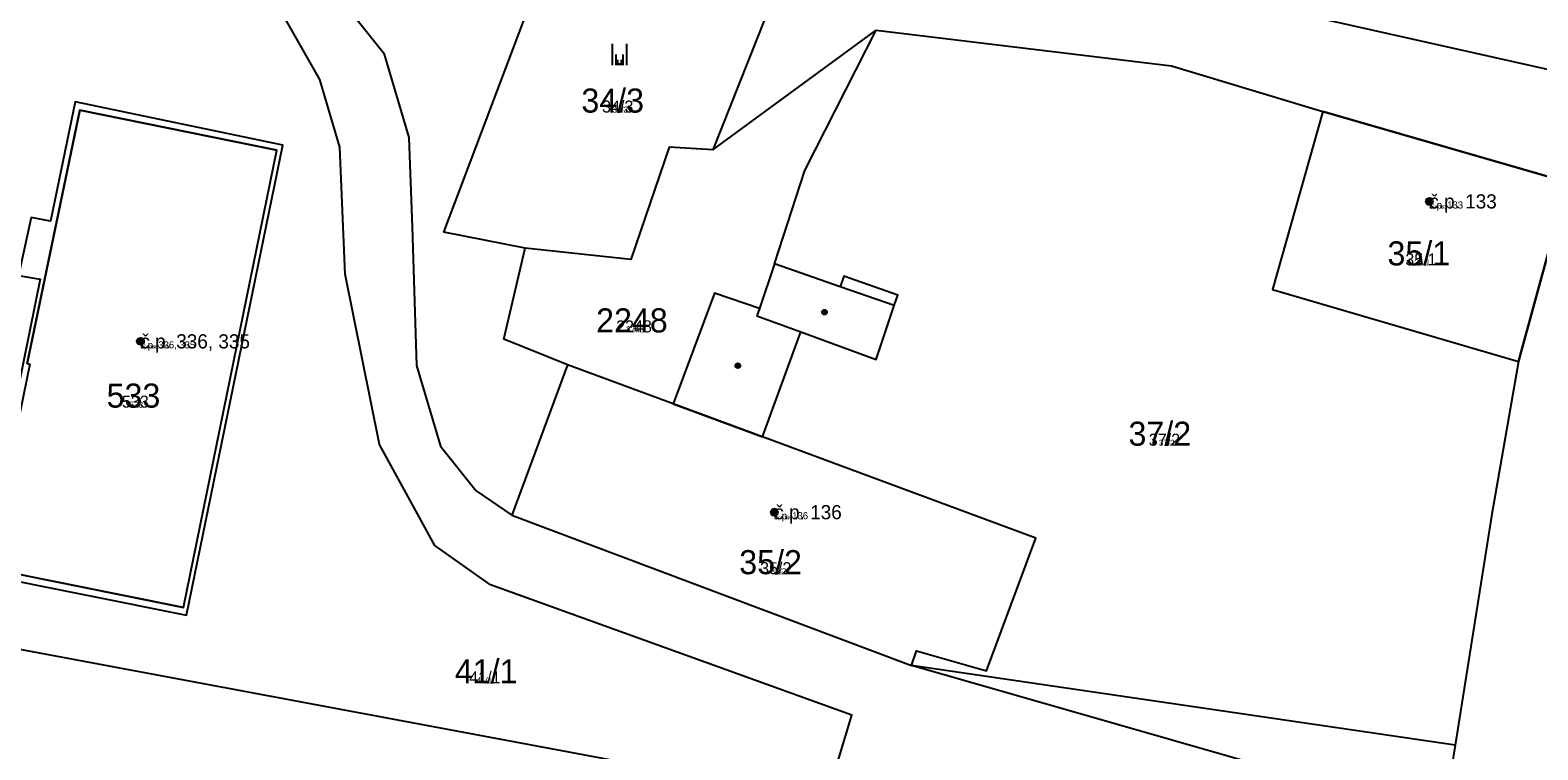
# Model space of a CAD drawing. Extents: x -744652 to -739090, y -980828 to -975855.
# Drawn here: x -742619.3 to -742512.8, y -978574.2 to -978523.4 of the extents above; entities that cross this region are included whole.
import ezdxf

# ---------------------------------------------------------------- set-up
doc = ezdxf.new("R2010")
doc.units = 0
for name, color, linetype in [('KAT_02_hranice parcel', 7, 'Continuous'), ('KAT_03_1000_st čísla parcelní', 7, 'Continuous'), ('KAT_03_1000_čísla parcelní', 7, 'Continuous'), ('KAT_03_1000_čísla popisná', 7, 'Continuous'), ('KAT_03_100_st čísla parcelní', 7, 'Continuous'), ('KAT_03_100_čísla parcelní', 7, 'Continuous'), ('KAT_03_100_čísla popisná', 7, 'Continuous'), ('KAT_03_250_st čísla parcelní', 7, 'Continuous'), ('KAT_03_250_čísla parcelní', 7, 'Continuous'), ('KAT_03_250_čísla popisná', 7, 'Continuous'), ('KAT_03_500_st čísla parcelní', 7, 'Continuous'), ('KAT_03_500_čísla parcelní', 7, 'Continuous'), ('KAT_03_500_čísla popisná', 7, 'Continuous'), ('KAT_04_vnitřní kresba', 7, 'Continuous'), ('KAT_05_1000_značky kultur', 7, 'Continuous'), ('KAT_05_100_značky kultur', 7, 'Continuous'), ('KAT_05_250_značky kultur', 7, 'Continuous'), ('KAT_05_500_značky kultur', 7, 'Continuous'), ('KAT_07_1000_značky budov', 7, 'Continuous'), ('KAT_07_100_značky budov', 7, 'Continuous'), ('KAT_07_500_značky budov', 7, 'Continuous'), ('KAT_14_plocha_budovy', 7, 'Continuous')]:
    doc.layers.add(name, color=color, linetype=linetype)

msp = doc.modelspace()

# ---------------------------------------------------------------- linework, layer by layer
at = {"layer": 'KAT_02_hranice parcel'}
for p, q in [((-742566.17, -978519.49), (-742571.06, -978531.84)), ((-742571.06, -978531.84), (-742559.54, -978523.41)), ((-742581.32, -978547.02), (-742585.26, -978557.63)), ((-742585.26, -978557.63), (-742557.03, -978568.25)), ((-742519.46, -978579.01), (-742557.03, -978568.25)), ((-742518.64, -978573.88), (-742557.03, -978568.25)), ((-742518.64, -978573.88), (-742519.46, -978579.01))]:
    msp.add_line(p, q, dxfattribs=at)
for points in [[(-742598.56, -978509.34), (-742606.7, -978509.52), (-742594.3, -978525.03), (-742592.54, -978530.97), (-742592.31, -978537.31), (-742591.99, -978547.07), (-742590.29, -978552.78), (-742587.77, -978555.92), (-742585.26, -978557.63)], [(-742520.5, -978587.81), (-742525.48, -978582.81), (-742528, -978581.12), (-742545.21, -978576.36), (-742546.31, -978580.73), (-742562.58, -978576.21), (-742561.25, -978571.75), (-742586.77, -978562.57), (-742590.71, -978559.78), (-742594.6, -978552.66), (-742597.04, -978540.63), (-742597.4, -978531.66), (-742598.83, -978526.88), (-742601.73, -978521.76), (-742606.95, -978517.23), (-742612.97, -978513.89), (-742622.3, -978510.73)], [(-742504.65, -978513.37), (-742508.75, -978526.92), (-742531.88, -978521.75), (-742534.32, -978519.68)], [(-742584.33, -978538.79), (-742590.07, -978537.66), (-742581.76, -978515.66), (-742566.17, -978519.49)], [(-742566.72, -978539.89), (-742564.56, -978533.31), (-742559.54, -978523.41)], [(-742559.54, -978523.41), (-742538.68, -978525.92), (-742527.99, -978529.15)], [(-742620.11, -978540.71), (-742618.57, -978540.99), (-742622.81, -978561.78), (-742608.23, -978564.71), (-742601.44, -978531.52), (-742616.11, -978528.47), (-742617.85, -978536.89), (-742619.2, -978536.62), (-742620.11, -978540.71)], [(-742527.99, -978529.15), (-742531.55, -978541.72), (-742514.17, -978546.79)], [(-742527.99, -978529.15), (-742510.7, -978534.14), (-742514.17, -978546.79)], [(-742571.06, -978531.84), (-742574.15, -978531.67), (-742576.86, -978539.59), (-742584.33, -978538.79)], [(-742581.32, -978547.02), (-742585.83, -978545.21), (-742584.33, -978538.79)], [(-742566.72, -978539.89), (-742567.78, -978543.06), (-742570.95, -978541.97), (-742573.86, -978549.78), (-742581.32, -978547.02)], [(-742557.03, -978568.25), (-742556.69, -978567.23), (-742551.75, -978568.62), (-742548.25, -978559.27), (-742567.57, -978552.11), (-742564.86, -978544.7), (-742559.54, -978546.66), (-742558.25, -978542.84), (-742558, -978542.1), (-742561.81, -978540.77), (-742562.08, -978541.51), (-742566.72, -978539.89)], [(-742514.17, -978546.79), (-742516.04, -978557.56), (-742518.64, -978573.88)], [(-742639.54, -978563.45), (-742574.84, -978575.54), (-742583.67, -978623.81)]]:
    msp.add_lwpolyline(points, dxfattribs=at)
at = {"layer": 'KAT_03_1000_čísla popisná'}
for centre in [(-742520.46, -978535.49), (-742520.46, -978535.49), (-742611.49, -978545.37), (-742611.49, -978545.37), (-742566.72, -978557.43), (-742566.72, -978557.43)]:
    msp.add_circle(centre, 0.25, dxfattribs=at)
at = {"layer": 'KAT_03_100_čísla popisná'}
for centre in [(-742520.46, -978535.49), (-742520.46, -978535.49), (-742611.49, -978545.37), (-742611.49, -978545.37), (-742566.72, -978557.43), (-742566.72, -978557.43)]:
    msp.add_circle(centre, 0.025, dxfattribs=at)
at = {"layer": 'KAT_03_250_čísla popisná'}
for centre in [(-742520.46, -978535.49), (-742520.46, -978535.49), (-742611.49, -978545.37), (-742611.49, -978545.37), (-742566.72, -978557.43), (-742566.72, -978557.43)]:
    msp.add_circle(centre, 0.0625, dxfattribs=at)
at = {"layer": 'KAT_03_500_čísla popisná'}
for centre in [(-742520.46, -978535.49), (-742520.46, -978535.49), (-742611.49, -978545.37), (-742611.49, -978545.37), (-742566.72, -978557.43), (-742566.72, -978557.43)]:
    msp.add_circle(centre, 0.125, dxfattribs=at)
at = {"layer": 'KAT_04_vnitřní kresba'}
for p, q in [((-742619.49, -978546.93), (-742615.78, -978529.04)), ((-742615.78, -978529.04), (-742601.87, -978531.88)), ((-742608.46, -978564.17), (-742601.87, -978531.88)), ((-742558.25, -978542.84), (-742562.08, -978541.51)), ((-742567.78, -978543.06), (-742567.95, -978543.56)), ((-742567.95, -978543.56), (-742564.86, -978544.7)), ((-742573.86, -978549.78), (-742567.57, -978552.11)), ((-742608.46, -978564.17), (-742622.23, -978561.39))]:
    msp.add_line(p, q, dxfattribs=at)
at = {"layer": 'KAT_05_1000_značky kultur'}
for p, q in [((-742578.15, -978525.87), (-742578.15, -978524.37)), ((-742577.15, -978525.87), (-742577.15, -978524.37))]:
    msp.add_line(p, q, dxfattribs=at)
at = {"layer": 'KAT_05_100_značky kultur'}
for p, q in [((-742577.69, -978525.87), (-742577.69, -978525.72)), ((-742577.59, -978525.87), (-742577.59, -978525.72))]:
    msp.add_line(p, q, dxfattribs=at)
at = {"layer": 'KAT_05_250_značky kultur'}
for p, q in [((-742577.77, -978525.87), (-742577.77, -978525.49)), ((-742577.52, -978525.87), (-742577.52, -978525.49))]:
    msp.add_line(p, q, dxfattribs=at)
at = {"layer": 'KAT_05_500_značky kultur'}
for p, q in [((-742577.9, -978525.87), (-742577.9, -978525.12)), ((-742577.4, -978525.87), (-742577.4, -978525.12))]:
    msp.add_line(p, q, dxfattribs=at)
at = {"layer": 'KAT_07_1000_značky budov'}
for centre in [(-742520.47, -978535.49), (-742563.18, -978543.31), (-742611.5, -978545.37), (-742569.3, -978547.09), (-742566.73, -978557.43)]:
    msp.add_circle(centre, 0.175, dxfattribs=at)
at = {"layer": 'KAT_07_100_značky budov'}
for centre in [(-742520.46, -978535.49), (-742563.17, -978543.31), (-742611.49, -978545.37), (-742569.29, -978547.09), (-742566.72, -978557.43)]:
    msp.add_circle(centre, 0.0175, dxfattribs=at)
at = {"layer": 'KAT_07_500_značky budov'}
for centre, radius in [((-742520.46, -978535.49), 0.0875), ((-742520.46, -978535.49), 0.0438), ((-742563.17, -978543.31), 0.0875), ((-742563.17, -978543.31), 0.0438), ((-742611.49, -978545.37), 0.0875), ((-742611.49, -978545.37), 0.0438), ((-742569.29, -978547.09), 0.0875), ((-742569.29, -978547.09), 0.0438), ((-742566.72, -978557.43), 0.0875), ((-742566.72, -978557.43), 0.0438)]:
    msp.add_circle(centre, radius, dxfattribs=at)
at = {"layer": 'KAT_14_plocha_budovy'}
for points in [[(-742622.23, -978561.39), (-742608.46, -978564.17), (-742601.87, -978531.88), (-742615.78, -978529.04), (-742619.49, -978546.93), (-742619.3, -978546.99), (-742620.48, -978552.74), (-742620.12, -978552.81), (-742620.56, -978554.95), (-742620.91, -978554.9)], [(-742531.55, -978541.72), (-742514.17, -978546.79), (-742510.7, -978534.14), (-742527.99, -978529.15)], [(-742585.26, -978557.63), (-742557.03, -978568.25), (-742556.69, -978567.23), (-742551.75, -978568.62), (-742548.25, -978559.27), (-742567.57, -978552.11), (-742573.86, -978549.78), (-742581.32, -978547.02)]]:
    msp.add_lwpolyline(points, close=True, dxfattribs=at)

# ---------------------------------------------------------------- texts
at = {"layer": 'KAT_03_1000_st čísla parcelní'}
for s, p in [('35/1', (-742523.42, -978540.01)), ('533', (-742613.88, -978550.05)), ('35/2', (-742569.2, -978561.81))]:
    msp.add_text(s, height=1.7, dxfattribs=at).set_placement(p)
at = {"layer": 'KAT_03_1000_čísla parcelní'}
for s, p in [('34/3', (-742580.35, -978529.22)), ('2248', (-742579.31, -978544.74)), ('37/2', (-742541.71, -978552.74)), ('41/1', (-742589.29, -978569.52))]:
    msp.add_text(s, height=1.7, dxfattribs=at).set_placement(p)
at = {"layer": 'KAT_03_1000_čísla popisná'}
for s, height, p in [('č.p. 133', 1, (-742520.46, -978535.99)), ('35/1', 0.017, (-742520.92, -978540.01)), ('č.p. 336, 335', 1, (-742611.49, -978545.87)), ('533', 0.017, (-742611.73, -978550.05)), ('č.p. 136', 1, (-742566.72, -978557.93)), ('35/2', 0.017, (-742566.28, -978561.81))]:
    msp.add_text(s, height=height, dxfattribs=at).set_placement(p)
at = {"layer": 'KAT_03_100_st čísla parcelní'}
for s, p in [('35/1', (-742521.14, -978540.01)), ('533', (-742611.93, -978550.05)), ('35/2', (-742566.54, -978561.81))]:
    msp.add_text(s, height=0.17, dxfattribs=at).set_placement(p)
at = {"layer": 'KAT_03_100_čísla parcelní'}
for s, p in [('34/3', (-742577.72, -978529.22)), ('2248', (-742576.78, -978544.74)), ('37/2', (-742539.13, -978552.74)), ('41/1', (-742587.45, -978569.52))]:
    msp.add_text(s, height=0.17, dxfattribs=at).set_placement(p)
at = {"layer": 'KAT_03_100_čísla popisná'}
for s, height, p in [('č.p. 133', 0.1, (-742520.46, -978535.99)), ('35/1', 0.0017, (-742520.89, -978540.01)), ('č.p. 336, 335', 0.1, (-742611.49, -978545.87)), ('533', 0.0017, (-742611.71, -978550.05)), ('č.p. 136', 0.1, (-742566.72, -978557.93)), ('35/2', 0.0017, (-742566.25, -978561.81))]:
    msp.add_text(s, height=height, dxfattribs=at).set_placement(p)
at = {"layer": 'KAT_03_250_st čísla parcelní'}
for s, p in [('35/1', (-742521.52, -978540.01)), ('533', (-742612.25, -978550.05)), ('35/2', (-742566.99, -978561.81))]:
    msp.add_text(s, height=0.425, dxfattribs=at).set_placement(p)
at = {"layer": 'KAT_03_250_čísla parcelní'}
for s, p in [('34/3', (-742578.16, -978529.22)), ('2248', (-742577.2, -978544.74)), ('37/2', (-742539.56, -978552.74)), ('41/1', (-742587.76, -978569.52))]:
    msp.add_text(s, height=0.425, dxfattribs=at).set_placement(p)
at = {"layer": 'KAT_03_250_čísla popisná'}
for s, height, p in [('č.p. 133', 0.25, (-742520.46, -978535.99)), ('35/1', 0.00425, (-742520.9, -978540.01)), ('č.p. 336, 335', 0.25, (-742611.49, -978545.87)), ('533', 0.00425, (-742611.71, -978550.05)), ('č.p. 136', 0.25, (-742566.72, -978557.93)), ('35/2', 0.00425, (-742566.26, -978561.81))]:
    msp.add_text(s, height=height, dxfattribs=at).set_placement(p)
at = {"layer": 'KAT_03_500_st čísla parcelní'}
for s, p in [('35/1', (-742522.16, -978540.01)), ('533', (-742612.8, -978550.05)), ('35/2', (-742567.73, -978561.81))]:
    msp.add_text(s, height=0.85, dxfattribs=at).set_placement(p)
at = {"layer": 'KAT_03_500_čísla parcelní'}
for s, p in [('34/3', (-742578.89, -978529.22)), ('2248', (-742577.9, -978544.74)), ('37/2', (-742540.28, -978552.74)), ('41/1', (-742588.27, -978569.52))]:
    msp.add_text(s, height=0.85, dxfattribs=at).set_placement(p)
at = {"layer": 'KAT_03_500_čísla popisná'}
for s, height, p in [('č.p. 133', 0.5, (-742520.46, -978535.99)), ('35/1', 0.0085, (-742520.9, -978540.01)), ('č.p. 336, 335', 0.5, (-742611.49, -978545.87)), ('533', 0.0085, (-742611.72, -978550.05)), ('č.p. 136', 0.5, (-742566.72, -978557.93)), ('35/2', 0.0085, (-742566.26, -978561.81))]:
    msp.add_text(s, height=height, dxfattribs=at).set_placement(p)

doc.saveas('drawing.dxf')
